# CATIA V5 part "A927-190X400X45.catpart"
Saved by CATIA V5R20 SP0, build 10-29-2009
Part number: A927-190X400X45
Source: Unknown
Property "A": "90.000"
Property "ARTICLENO": "A927-190X400X45"
Property "BOMINFO": "A927-190X400X45"
Property "CODE": "A927-190X400X45"
Property "CREATOR": "CADENAS GmbH"
Property "D": "22.000"
Property "D1": "33.000"
Property "F": "36.000"
Property "FORM": "B"
Property "L": "400.000"
Property "L1": "150.000"
Property "L2": "40.000"
Property "L3": "80.000"
Property "LINA": "A927-190X400X45"
Property "NB": "A927-190X400X45"
Property "NBSYN": "$CODE."
Property "NN": "A927"
Property "NT": "VDI 3387 Removable Die Heels, steel and self-lubricating"
Property "R": "31.500"
Property "S": "45.000"
Property "SUPPLIER": "CF"
Property "T": "25.500"
Property "W": "190.000"
Bounding box of the stored display mesh (mm): x -95 to 95, y 0 to 400, z -45 to 0
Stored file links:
  C:\Users\borellobunino\Desktop\3D X SITO CF\A927\GSB_OILLESS_G2290519040045\CATIAV5\A927-190X400X45.catpart
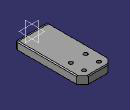
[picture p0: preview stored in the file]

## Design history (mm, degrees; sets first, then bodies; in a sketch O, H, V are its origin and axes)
Body1 "Geometry.1" (main body)
  Solid1 "A927-190X400X45.catpart": solid without history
